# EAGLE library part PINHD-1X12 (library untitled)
PIN HEADER
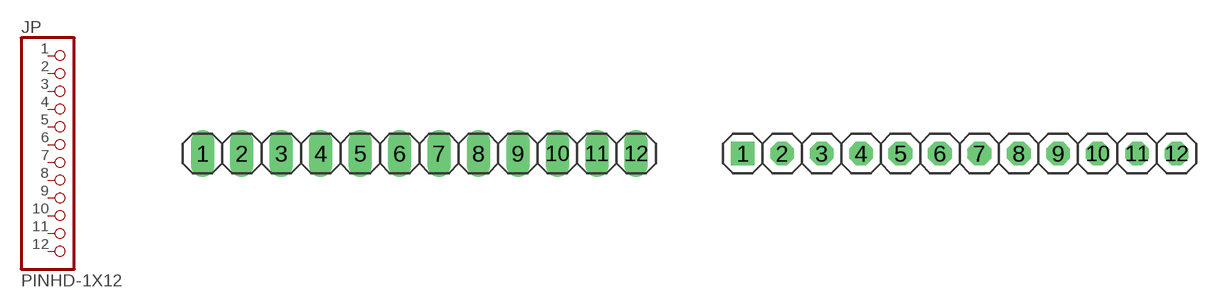
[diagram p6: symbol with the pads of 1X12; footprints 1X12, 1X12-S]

Designator prefix JP

## PINHD-1X12_2.54  [1X12]
1  1  pas
2  2  pas
3  3  pas
4  4  pas
5  5  pas
6  6  pas
7  7  pas
8  8  pas
9  9  pas
10  10  pas
11  11  pas
12  12  pas

## PINHD-1X12_2.54-S  [1X12-S]
Pads as for 1X12

## PINHD-1X12_2.54-90°  [1X12/90]
Pads as for 1X12

## PINHD-1X12_2.54-90°-S  [1X12/90-S]
Pads as for 1X12

## PINHD-1X12_2.00  [1X12M]
Pads as for 1X12

## PINHD-1X12_2.54-SMD  [1X12SMD]
Pads as for 1X12

## PINHD-1X12_2.54-SMD-90°  [1X12SMD/90]
Pads as for 1X12

## Footprint 1X12 (pad centres in mm)
PIN HEADER - 2.54
drill 1.016 long: 1 -13.97,0; 2 -11.43,0; 3 -8.89,0; 4 -6.35,0; 5 -3.81,0; 6 -1.27,0; 7 1.27,0; 8 3.81,0; 9 6.35,0; 10 8.89,0; 11 11.43,0; 12 13.97,0

## Footprint 1X12-S (pad centres in mm)
PIN HEADER - 2.54
drill 1.016 square: 1 -13.97,0
drill 1.016 octagon: 2 -11.43,0; 3 -8.89,0; 4 -6.35,0; 5 -3.81,0; 6 -1.27,0; 7 1.27,0; 8 3.81,0; 9 6.35,0; 10 8.89,0; 11 11.43,0; 12 13.97,0

## Footprint 1X12/90 (pad centres in mm)
PIN HEADER - 2.54 90°
drill 1.016 long: 1 -13.97,-3.81; 2 -11.43,-3.81; 3 -8.89,-3.81; 4 -6.35,-3.81; 5 -3.81,-3.81; 6 -1.27,-3.81; 7 1.27,-3.81; 8 3.81,-3.81; 9 6.35,-3.81; 10 8.89,-3.81; 11 11.43,-3.81; 12 13.97,-3.81

## Footprint 1X12/90-S (pad centres in mm)
PIN HEADER - 2.54 90°
drill 1.016 square: 1 -13.97,-3.81
drill 1.016 octagon: 2 -11.43,-3.81; 3 -8.89,-3.81; 4 -6.35,-3.81; 5 -3.81,-3.81; 6 -1.27,-3.81; 7 1.27,-3.81; 8 3.81,-3.81; 9 6.35,-3.81; 10 8.89,-3.81; 11 11.43,-3.81; 12 13.97,-3.81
